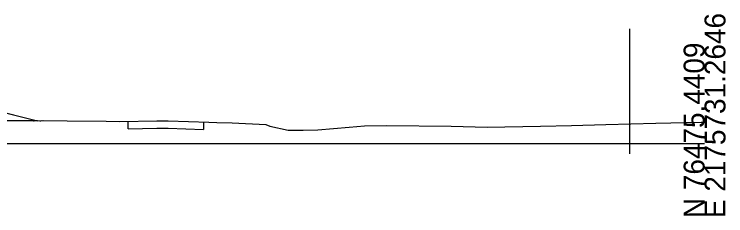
# Model space of a CAD drawing. Extents: x 2177029 to 2201446, y 59897 to 78390.
# Drawn here: x 2199350.3 to 2199445.6, y 61397.6 to 61424.6 of the extents above; entities that cross this region are included whole.
import ezdxf

# ---------------------------------------------------------------- set-up
doc = ezdxf.new("R2010")
doc.units = 0
for name, color, linetype in [('Exist Cross Section Cell', 7, 'Continuous'), ('Exist PHM Roadway Shape', 7, 'Continuous'), ('Exist XS Ground Line', 7, 'Continuous'), ('Prop CMT Pvmt Wedge Surface 1', 7, 'Continuous'), ('Prop Hatching', 7, 'Continuous'), ('Prop XS Side Slope Text', 7, 'Continuous'), ('Scratch_Level_2', 7, 'Continuous')]:
    doc.layers.add(name, color=color, linetype=linetype)

msp = doc.modelspace()

# ---------------------------------------------------------------- linework, layer by layer
at = {"layer": 'Exist Cross Section Cell'}
msp.add_line((2199242.732, 61407.31), (2199442.732, 61407.31), dxfattribs=at)
at = {"layer": 'Exist XS Ground Line'}
msp.add_lwpolyline([(2199347.409, 61410.375), (2199357.38, 61410.342), (2199362.575, 61410.276), (2199364.428, 61410.272), (2199369.369, 61410.341), (2199370.873, 61410.353), (2199376.322, 61410.162), (2199377.398, 61410.113), (2199379.453, 61410.071), (2199383.959, 61409.853), (2199384.496, 61409.637), (2199386.96, 61409.077), (2199388.424, 61409.087), (2199388.979, 61409.097), (2199390.956, 61409.135), (2199395.153, 61409.476), (2199397.184, 61409.664), (2199400.175, 61409.714), (2199408.777, 61409.62), (2199413.612, 61409.493), (2199420.77, 61409.635), (2199424.906, 61409.72), (2199429.497, 61409.842), (2199436.188, 61410.045), (2199442.299, 61410.171), (2199442.732, 61410.178)], dxfattribs=at)
at = {"layer": 'Prop CMT Pvmt Wedge Surface 1'}
for p, q in [((2199365.528, 61409.287), (2199365.528, 61410.287)), ((2199365.528, 61409.287), (2199369.369, 61409.341)), ((2199369.369, 61409.341), (2199370.873, 61409.353)), ((2199370.873, 61409.353), (2199375.612, 61409.187)), ((2199375.612, 61410.187), (2199375.612, 61409.187))]:
    msp.add_line(p, q, dxfattribs=at)
at = {"layer": 'Prop Hatching'}
msp.add_lwpolyline([(2199332.397, 61415.108), (2199334.397, 61415.108), (2199353.41, 61410.355)], dxfattribs=at)
at = {"layer": 'Prop XS Side Slope Text'}
msp.add_lwpolyline([(2199338.397, 61414.108), (2199353.41, 61410.355), (2199347.409, 61410.375), (2199344.838, 61410.346), (2199341.643, 61410.166), (2199333.133, 61409.605), (2199328.543, 61410.402), (2199311.947, 61413.182), (2199308.234, 61413.259), (2199322.387, 61414.108), (2199333.396, 61414.108)], close=True, dxfattribs=at)
at = {"layer": 'Scratch_Level_2'}
msp.add_line((2199432.732, 61405.938), (2199432.732, 61422.682), dxfattribs=at)

# ---------------------------------------------------------------- texts
at = {"layer": 'Exist Cross Section Cell'}
for s, p in [('E 2175731.2646', (2199445.532, 61397.31)), ('N 76475.4409', (2199442.732, 61397.31))]:
    msp.add_text(s, height=2.8, rotation=90, dxfattribs=at).set_placement(p)
at = {"layer": 'Exist PHM Roadway Shape'}
msp.add_text('RT_Slope_Fill', height=0.2, dxfattribs=at).set_placement((2199352.457, 61410.255))

doc.saveas('drawing.dxf')
